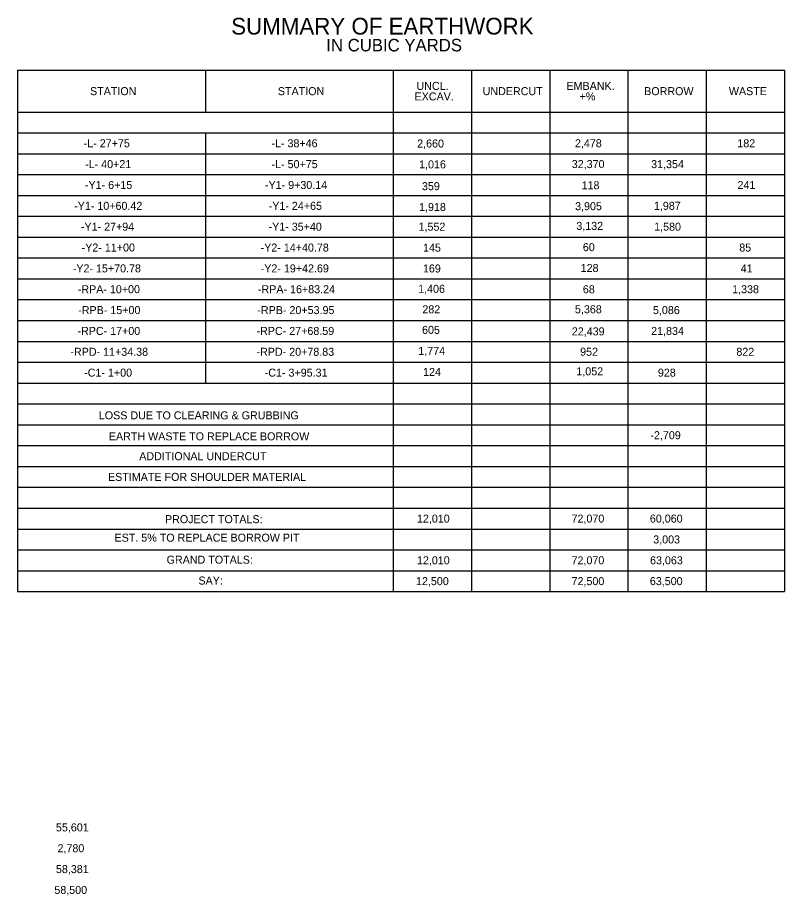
# Model space of a CAD drawing. Extents: x 573692 to 577281, y -53325 to -51406.
# Drawn here: x 575479 to 576053, y -52064 to -51406 of the extents above; entities that cross this region are included whole.
import ezdxf

# ---------------------------------------------------------------- set-up
doc = ezdxf.new("R2010")
doc.units = 0
doc.layers.add('Prop EOT', color=7, linetype='Continuous')
doc.layers.add('Sheet North Arrow CELL', color=7, linetype='Continuous')

msp = doc.modelspace()

# ---------------------------------------------------------------- linework, layer by layer
at = {"layer": 'Prop EOT'}
for p, q in [((575702.24, -51445.32), (575702.24, -51445.32)), ((575710.05, -51445.45), (575710.05, -51445.45)), ((575721.37, -51445.2), (575721.37, -51445.2)), ((575728.37, -51445.32), (575728.37, -51445.32))]:
    msp.add_line(p, q, dxfattribs=at)
at = {"layer": 'Sheet North Arrow CELL'}
for p, q in [((575478.62, -51445.26), (576053.24, -51445.26)), ((575478.62, -51445.26), (575478.62, -51835.88)), ((575619.37, -51445.26), (575619.37, -51476.51)), ((575760.12, -51445.26), (575760.12, -51835.88)), ((575818.74, -51445.26), (575818.74, -51835.88)), ((575877.37, -51445.26), (575877.37, -51835.88)), ((575935.99, -51445.26), (575935.99, -51835.88)), ((575994.62, -51445.26), (575994.62, -51835.88)), ((576053.24, -51445.26), (576053.24, -51835.88)), ((575478.58, -51476.51), (576053.24, -51476.51)), ((575478.62, -51492.13), (576053.24, -51492.13)), ((575619.37, -51492.13), (575619.37, -51679.63)), ((575478.62, -51507.76), (576053.24, -51507.76)), ((575478.62, -51523.38), (576053.24, -51523.38)), ((575478.62, -51539.01), (576053.24, -51539.01)), ((575478.62, -51554.63), (576053.24, -51554.63)), ((575478.62, -51570.26), (576053.24, -51570.26)), ((575478.62, -51585.88), (576053.24, -51585.88)), ((575478.62, -51601.51), (576053.24, -51601.51)), ((575478.62, -51617.13), (576053.24, -51617.13)), ((575478.62, -51632.76), (576053.24, -51632.76)), ((575478.62, -51648.38), (576053.24, -51648.38)), ((575478.62, -51664.01), (576053.24, -51664.01)), ((575478.62, -51679.63), (576053.24, -51679.63)), ((575478.62, -51695.26), (576053.24, -51695.26)), ((575478.62, -51710.88), (576053.24, -51710.88)), ((575478.62, -51726.51), (576053.24, -51726.51)), ((575478.62, -51742.08), (576053.24, -51742.08)), ((575478.62, -51757.76), (576053.24, -51757.76)), ((575478.62, -51773.38), (576053.24, -51773.38)), ((575478.62, -51789.01), (576053.24, -51789.01)), ((575478.62, -51804.63), (576053.24, -51804.63)), ((575478.62, -51820.26), (576053.24, -51820.26)), ((575478.62, -51835.88), (576053.24, -51835.88))]:
    msp.add_line(p, q, dxfattribs=at)

# ---------------------------------------------------------------- texts
at = {"layer": 'Prop EOT'}
for s, height, p in [('SUMMARY OF EARTHWORK', 12.5001, (575638.68, -51418.45)), ('IN CUBIC YARDS', 9.3751, (575709.92, -51431.09))]:
    msp.add_text(s, height=height, rotation=0.01193, dxfattribs=at).set_placement(p)
for s, p in [('STATION', (575532.87, -51463.88)), ('STATION', (575673.64, -51463.88)), ('UNCL.', (575777.5, -51459.95)), ('UNDERCUT', (575827.07, -51463.88)), ('EMBANK.', (575889.9, -51459.95)), ('BORROW', (575948.14, -51463.88)), ('WASTE', (576011.6, -51463.88)), ('EXCAV.', (575776.06, -51467.82)), ('+%', (575899.75, -51467.82)), ('-L- 27+75', (575528.13, -51502.95)), ('-L- 38+46', (575668.8, -51502.95)), ('2,660', (575778.02, -51503.12)), ('2,478', (575896.26, -51502.91)), ('182', (576017.94, -51502.95)), ('-L- 40+21', (575529.2, -51518.57)), ('-L- 50+75', (575668.9, -51518.57)), ('1,016', (575779.47, -51518.74)), ('32,370', (575893.88, -51518.53)), ('31,354', (575953.36, -51518.57)), ('-Y1- 6+15', (575529.09, -51534.2)), ('-Y1- 9+30.14', (575663.97, -51534.2)), ('359', (575781.63, -51535.08)), ('118', (575901.25, -51534.47)), ('241', (576018.08, -51534.2)), ('-Y1- 10+60.42', (575520.99, -51549.82)), ('-Y1- 24+65', (575666.77, -51549.82)), ('1,918', (575779.46, -51550.7)), ('3,905', (575896.37, -51550.09)), ('1,987', (575955.43, -51549.82)), ('-Y1- 27+94', (575526.04, -51565.45)), ('-Y1- 35+40', (575666.65, -51565.45)), ('1,552', (575779.06, -51565.46)), ('3,132', (575897.3, -51564.85)), ('1,580', (575955.63, -51565.45)), ('-Y2- 11+00', (575526.6, -51581.07)), ('-Y2- 14+40.78', (575660.72, -51581.07)), ('145', (575782.42, -51581.13)), ('60', (575902.18, -51580.79)), ('85', (576019.4, -51581.07)), ('-Y2- 15+70.78', (575519.95, -51596.7)), ('-Y2- 19+42.69', (575660.77, -51596.7)), ('169', (575782.35, -51596.75)), ('128', (575900.54, -51596.41)), ('41', (576020.46, -51596.7)), ('-RPA- 10+00', (575523.69, -51612.32)), ('-RPA- 16+83.24', (575658.69, -51612.32)), ('1,406', (575778.76, -51612.01)), ('68', (575902.19, -51612.35)), ('1,338', (576014.07, -51612.32)), ('-RPB- 15+00', (575524.02, -51627.95)), ('-RPB- 20+53.95', (575658.26, -51627.95)), ('282', (575781.91, -51627.39)), ('5,368', (575896.26, -51627.34)), ('5,086', (575954.74, -51627.95)), ('605', (575781.7, -51642.78)), ('-RPC- 17+00', (575523.47, -51643.57)), ('-RPC- 27+68.59', (575657.64, -51643.57)), ('22,439', (575893.93, -51643.91)), ('21,834', (575953.36, -51643.57)), ('-RPD- 11+34.38', (575518.17, -51659.2)), ('-RPD- 20+78.83', (575657.63, -51659.2)), ('1,774', (575778.9, -51658.56)), ('952', (575900.14, -51659.16)), ('822', (576017.22, -51659.2)), ('-C1- 1+00', (575528.48, -51674.82)), ('-C1- 3+95.31', (575663.78, -51674.82)), ('124', (575782.46, -51674.26)), ('1,052', (575897.3, -51673.84)), ('928', (575958.41, -51674.82)), ('LOSS DUE TO CLEARING & GRUBBING', (575539.49, -51706.82)), ('-2,709', (575952.8, -51721.7)), ('ADDITIONAL UNDERCUT', (575569.74, -51737.42)), ('ESTIMATE FOR SHOULDER MATERIAL', (575546.36, -51752.96)), ('PROJECT TOTALS:', (575589.05, -51784.63)), ('12,010', (575777.86, -51784.2)), ('72,070', (575893.72, -51784.2)), ('60,060', (575952.4, -51784.2)), ('EST. 5% TO REPLACE BORROW PIT', (575551.23, -51798.49)), ('3,003', (575954.91, -51799.82)), ('GRAND TOTALS:', (575590.28, -51815)), ('12,010', (575777.86, -51815.45)), ('72,070', (575893.72, -51815.45)), ('63,063', (575952.54, -51815.45)), ('SAY:', (575614.12, -51830.63)), ('12,500', (575777.15, -51831.07)), ('72,500', (575893.72, -51831.07)), ('63,500', (575952.4, -51831.07)), ('55,601', (575507.34, -52015.62)), ('2,780', (575508.52, -52031.24)), ('58,381', (575507.34, -52046.87)), ('58,500', (575506.15, -52062.49))]:
    msp.add_text(s, height=6, dxfattribs=at).set_placement(p)
at = {"layer": 'Sheet North Arrow CELL'}
msp.add_text('EARTH WASTE TO REPLACE BORROW', height=6, dxfattribs=at).set_placement((575546.97, -51722.57))

doc.saveas('drawing.dxf')
